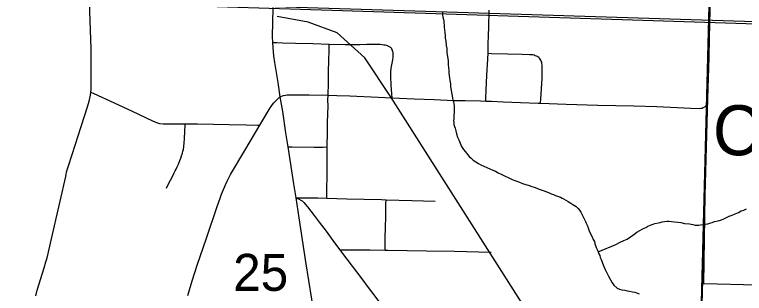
# Model space of a CAD drawing. Extents: x 0 to 34, y 0 to 22.
# Drawn here: x 6.646 to 7.471, y 17.868 to 18.183 of the extents above; entities that cross this region are included whole.
import ezdxf

# ---------------------------------------------------------------- set-up
doc = ezdxf.new("R2010")
doc.units = 0
for name, color, linetype in [('Default', 7, 'Continuous'), ('GM_X_City_Street', 7, 'Continuous'), ('GM_X_County_Road', 7, 'Continuous'), ('GM_X_Minor_River', 7, 'Continuous'), ('GM_X_Rail_Line', 7, 'Continuous'), ('GM_X_Rail_Line_Text', 7, 'Continuous'), ('GM_X_Section', 7, 'Continuous'), ('GM_X_Section_Text', 7, 'Continuous'), ('GM_X_State_Route', 7, 'Continuous'), ('GM_X_Township_Road', 7, 'Continuous')]:
    doc.layers.add(name, color=color, linetype=linetype)

msp = doc.modelspace()

# ---------------------------------------------------------------- linework, layer by layer
at = {"layer": 'Default'}
msp.add_lwpolyline([(7.60459, 17.87419), (7.42494, 17.87863), (7.42778, 18.08122), (7.42892, 18.08581), (7.43183, 18.18894), (7.43397, 18.27475), (7.49781, 18.27299)], dxfattribs=at)
at = {"layer": 'GM_X_City_Street'}
for points in [[(6.66995, 17.86509), (6.6718, 17.87167), (6.67964, 17.89667), (6.68158, 17.90343), (6.68288, 17.90825), (6.68405, 17.91306), (6.68665, 17.92457), (6.69778, 17.9723), (6.70401, 17.9999), (6.70441, 18.00259), (6.70493, 18.00506), (6.70597, 18.00857), (6.70707, 18.01197), (6.71102, 18.02513), (6.72129, 18.05646), (6.72863, 18.07888), (6.73032, 18.08537), (6.73102, 18.08861), (6.73178, 18.09212), (6.73229, 18.09536), (6.73257, 18.09798), (6.73264, 18.10115), (6.73267, 18.11044), (6.73263, 18.14434), (6.73081, 18.19753)], [(7.17857, 18.08537), (7.1787, 18.08827), (7.17915, 18.09805), (7.17991, 18.11436), (7.18078, 18.13301), (7.18105, 18.13942), (7.18133, 18.14872), (7.1817, 18.16082), (7.18191, 18.16789), (7.18212, 18.17483), (7.18234, 18.18201), (7.18252, 18.18822)], [(6.93736, 18.15169), (6.94245, 18.15155), (6.94865, 18.15137), (6.96352, 18.15094), (6.98329, 18.15038), (7.00154, 18.14987), (7.01963, 18.14948), (7.03069, 18.14938), (7.03617, 18.14951), (7.04424, 18.14971), (7.04845, 18.14987), (7.0526, 18.14989), (7.05912, 18.14967), (7.06151, 18.14945), (7.06327, 18.14919), (7.06486, 18.14889), (7.0662, 18.14856), (7.06716, 18.14825), (7.06799, 18.14788), (7.06864, 18.14756), (7.06944, 18.14708), (7.07021, 18.14659), (7.0709, 18.14599), (7.07146, 18.14544), (7.07198, 18.14479), (7.07252, 18.14392)], [(6.99877, 17.97563), (6.99882, 17.97899), (6.99922, 18.00755), (6.9993, 18.02807), (6.99939, 18.03345), (6.9997, 18.05078), (6.99971, 18.06122), (7.00041, 18.07984), (7.00025, 18.08645), (7.00036, 18.09209), (7.00066, 18.10569), (7.00094, 18.11877), (7.00153, 18.143), (7.00154, 18.14485), (7.00154, 18.14987)], [(7.0726, 18.08891), (7.07229, 18.09376), (7.07165, 18.10357), (7.07114, 18.11334), (7.07122, 18.11762), (7.07168, 18.12251), (7.07349, 18.13211), (7.07386, 18.13506), (7.07395, 18.13773), (7.0739, 18.13898), (7.07376, 18.14017), (7.07358, 18.14115), (7.0733, 18.14208), (7.07302, 18.143), (7.07252, 18.14392)], [(7.18105, 18.13942), (7.18497, 18.13932), (7.20314, 18.13885), (7.21981, 18.13834), (7.22813, 18.13825), (7.22997, 18.13814), (7.23167, 18.13794), (7.23304, 18.13756), (7.23443, 18.13711), (7.23647, 18.13618)], [(7.24046, 18.083), (7.24083, 18.08805), (7.24207, 18.11096), (7.24243, 18.12276), (7.24227, 18.1256), (7.24206, 18.12772), (7.24171, 18.12929), (7.24129, 18.13072), (7.24082, 18.13185), (7.24017, 18.13294), (7.23942, 18.13389), (7.23852, 18.13479), (7.23749, 18.13556), (7.23647, 18.13618)], [(6.73229, 18.09536), (6.73547, 18.09392), (6.75877, 18.08341), (6.77911, 18.07405), (6.80179, 18.06289), (6.80461, 18.06175), (6.80635, 18.06105), (6.80994, 18.06019), (6.81408, 18.05982), (6.82519, 18.05966), (6.83246, 18.05972), (6.83863, 18.05978), (6.85275, 18.0595), (6.87091, 18.05912), (6.8885, 18.0588), (6.90795, 18.05843), (6.92065, 18.0582), (6.92337, 18.05815)], [(6.92337, 18.05815), (6.92666, 18.06368), (6.93277, 18.07404), (6.9349, 18.07765), (6.93591, 18.0793), (6.93743, 18.08137), (6.9391, 18.08326), (6.9424, 18.08695), (6.946, 18.09033)], [(6.946, 18.09033), (6.9499, 18.09168), (6.95238, 18.09224), (6.95413, 18.09247), (6.95615, 18.0926), (6.96549, 18.09254), (6.97907, 18.0926), (7.00036, 18.09209)], [(7.00036, 18.09209), (7.01008, 18.09172), (7.02511, 18.09117), (7.05706, 18.08963), (7.0726, 18.08891)], [(7.0726, 18.08891), (7.09754, 18.08806), (7.12026, 18.08714), (7.1422, 18.08623), (7.15525, 18.08595), (7.17256, 18.0856), (7.17857, 18.08537)], [(7.17857, 18.08537), (7.18518, 18.08512), (7.19803, 18.08462), (7.21769, 18.08377), (7.23757, 18.0831), (7.24046, 18.083)], [(7.24046, 18.083), (7.26926, 18.082), (7.30529, 18.08072), (7.34568, 18.07988), (7.3718, 18.07909), (7.41042, 18.07752), (7.41958, 18.07714), (7.42163, 18.07724), (7.42291, 18.07752), (7.42423, 18.07796), (7.4259, 18.07883), (7.42802, 18.08067)], [(6.81786, 17.98696), (6.82057, 17.99242), (6.82406, 17.99943), (6.82657, 18.00424), (6.8277, 18.00664), (6.82868, 18.00849), (6.82982, 18.01094), (6.83125, 18.01398), (6.8329, 18.01807), (6.83389, 18.02079), (6.83481, 18.02346), (6.83578, 18.02654), (6.83629, 18.02869), (6.83679, 18.03074), (6.83733, 18.03391), (6.83781, 18.03797), (6.83825, 18.04264), (6.83863, 18.05143), (6.8387, 18.05832), (6.83863, 18.05978)], [(6.84175, 17.86551), (6.84694, 17.88192), (6.85283, 17.90083), (6.86256, 17.92903), (6.87509, 17.96607), (6.87825, 17.97551), (6.87999, 17.98025), (6.88209, 17.98537), (6.88435, 17.99051), (6.88623, 17.99464), (6.88791, 17.99798), (6.89019, 18.00226), (6.90633, 18.02951), (6.92337, 18.05815)], [(6.95486, 18.03346), (6.95962, 18.03345), (6.98479, 18.03343), (6.99481, 18.03344), (6.99939, 18.03345)], [(6.96381, 17.97584), (6.97508, 17.97588), (6.98879, 17.97592), (6.99877, 17.97563), (7.02165, 17.97496), (7.06071, 17.97387), (7.06586, 17.97374), (7.09481, 17.97303), (7.12151, 17.97221)], [(7.06469, 17.91673), (7.06477, 17.92055), (7.06498, 17.93078), (7.06547, 17.95458), (7.06576, 17.96912), (7.06586, 17.97374)], [(7.01374, 17.917), (7.02071, 17.91698), (7.04763, 17.91694), (7.06469, 17.91673), (7.06803, 17.91669), (7.11156, 17.91616), (7.14332, 17.91562), (7.1703, 17.91502), (7.1845, 17.91465)]]:
    msp.add_lwpolyline(points, dxfattribs=at)
at = {"layer": 'GM_X_County_Road'}
for points in [[(6.96381, 17.97584), (6.96702, 17.97463), (6.96972, 17.97344), (6.97091, 17.97268), (6.97181, 17.97194), (6.97298, 17.97073), (6.97707, 17.96562), (6.98461, 17.95586), (6.99031, 17.94849), (6.99816, 17.93807), (7.00778, 17.92508), (7.01374, 17.917)], [(7.01374, 17.917), (7.01552, 17.91458), (7.0215, 17.90668), (7.03244, 17.8924), (7.03837, 17.88449), (7.04575, 17.87466), (7.04937, 17.86972), (7.06093, 17.85421)]]:
    msp.add_lwpolyline(points, dxfattribs=at)
at = {"layer": 'GM_X_Minor_River'}
for points in [[(7.12949, 18.18644), (7.12977, 18.18301), (7.13007, 18.18034), (7.13075, 18.17766), (7.13108, 18.17575), (7.13103, 18.17385), (7.13133, 18.17118), (7.13164, 18.16889)], [(7.13164, 18.16889), (7.13193, 18.16584), (7.13222, 18.16279), (7.13251, 18.15974), (7.1328, 18.15669), (7.13346, 18.15325), (7.1337, 18.1483), (7.13436, 18.14486), (7.13461, 18.14029), (7.13522, 18.13533), (7.13586, 18.13113), (7.13612, 18.12694), (7.13639, 18.12313), (7.13668, 18.12008), (7.13697, 18.11703), (7.13727, 18.11436), (7.13758, 18.11169), (7.13787, 18.10864), (7.13852, 18.10482), (7.13881, 18.10177), (7.13911, 18.09909), (7.14041, 18.09145), (7.14109, 18.08877), (7.1414, 18.08648), (7.14211, 18.08456), (7.14242, 18.08227), (7.14275, 18.08036), (7.14266, 18.07732), (7.14297, 18.07503), (7.1429, 18.07275), (7.1424, 18.06858), (7.14235, 18.06668), (7.14229, 18.06478), (7.14224, 18.06288), (7.14256, 18.06097), (7.14251, 18.05908), (7.1432, 18.05677), (7.1439, 18.05485), (7.14458, 18.05179), (7.14561, 18.04834), (7.14664, 18.04451), (7.14807, 18.04142), (7.14949, 18.03796), (7.15128, 18.03411), (7.15346, 18.03062), (7.15566, 18.0279), (7.15785, 18.02479), (7.15969, 18.02284), (7.16191, 18.02087), (7.16412, 18.01853), (7.16748, 18.01653), (7.17047, 18.01492), (7.17309, 18.01333), (7.17646, 18.01171), (7.17983, 18.01009), (7.18321, 18.00885), (7.18658, 18.00724), (7.18959, 18.00601), (7.19258, 18.0044), (7.19595, 18.00278), (7.19969, 18.00077), (7.20457, 17.99873), (7.20831, 17.99672), (7.21244, 17.99508), (7.21658, 17.99382), (7.21995, 17.9922), (7.22371, 17.99096), (7.22748, 17.98971), (7.23049, 17.98886), (7.23313, 17.98802), (7.23989, 17.98555), (7.24327, 17.98431), (7.24628, 17.98308), (7.24928, 17.98186), (7.25228, 17.98063), (7.25492, 17.97979), (7.25716, 17.97859), (7.26054, 17.97735), (7.2628, 17.97652), (7.26468, 17.97571), (7.26655, 17.97489), (7.26916, 17.9733), (7.27178, 17.9717), (7.27477, 17.97009), (7.277, 17.96851), (7.27887, 17.96731), (7.28073, 17.96612), (7.28294, 17.96377), (7.2844, 17.96183), (7.28587, 17.95989), (7.28694, 17.95758), (7.28839, 17.95525), (7.29018, 17.9514), (7.29125, 17.94909), (7.29196, 17.94717), (7.29303, 17.94485), (7.29409, 17.94216), (7.29551, 17.9387), (7.29693, 17.93524), (7.29872, 17.93176), (7.29978, 17.92869)], [(7.30545, 17.91484), (7.32544, 17.92301), (7.33046, 17.92591), (7.33469, 17.92768), (7.33815, 17.9291), (7.34591, 17.93459), (7.3494, 17.93715), (7.35249, 17.93896), (7.35519, 17.9404), (7.3575, 17.94148), (7.35943, 17.94256), (7.36175, 17.94402), (7.36367, 17.94472), (7.36559, 17.94543), (7.36751, 17.94613), (7.36943, 17.94684), (7.37364, 17.94785), (7.37555, 17.94818), (7.37785, 17.94888), (7.38052, 17.94918), (7.38318, 17.94948), (7.38584, 17.9494), (7.3885, 17.94933), (7.3919, 17.94885), (7.39568, 17.94836), (7.39909, 17.94788), (7.40324, 17.947), (7.40892, 17.94646), (7.41232, 17.9456), (7.41496, 17.94514), (7.41724, 17.94508), (7.41914, 17.94502), (7.42105, 17.94535), (7.42371, 17.94565), (7.42677, 17.94632), (7.42944, 17.94663), (7.43174, 17.94732), (7.43442, 17.948), (7.43711, 17.94907), (7.44132, 17.95009), (7.44476, 17.95113), (7.44746, 17.95219), (7.45053, 17.95362), (7.45361, 17.95506), (7.45707, 17.95648), (7.46053, 17.9579), (7.46399, 17.95932), (7.46708, 17.96113), (7.47015, 17.96218), (7.47323, 17.96362)], [(7.29978, 17.92869), (7.30123, 17.92637), (7.30192, 17.92407), (7.30263, 17.92215), (7.30332, 17.91984), (7.30439, 17.91753), (7.30545, 17.91484), (7.30614, 17.91254), (7.30723, 17.91061), (7.30792, 17.9083), (7.309, 17.90637), (7.30971, 17.90445), (7.3104, 17.90215), (7.31181, 17.89831), (7.31361, 17.89483), (7.31539, 17.89098), (7.31719, 17.8875), (7.32153, 17.87977), (7.32335, 17.87706), (7.32706, 17.87391), (7.32968, 17.8727), (7.33231, 17.87186), (7.33572, 17.87138), (7.33836, 17.87092), (7.34101, 17.87047), (7.3444, 17.86961), (7.34705, 17.86915), (7.34892, 17.86834), (7.35194, 17.86749)]]:
    msp.add_lwpolyline(points, dxfattribs=at)
at = {"layer": 'GM_X_Rail_Line'}
for points in [[(5.35106, 18.04678), (5.42697, 18.05726), (5.49719, 18.07056), (5.53225, 18.08015), (5.65152, 18.10637), (5.73788, 18.12707), (5.81793, 18.14439), (5.93217, 18.17031), (5.99402, 18.1844), (6.05215, 18.19648), (6.1174, 18.20707), (6.18087, 18.21236), (6.22876, 18.21488), (6.43848, 18.20909), (6.70994, 18.20004), (7.11057, 18.18722), (7.54287, 18.1734)], [(5.35138, 18.04432), (5.42737, 18.05481), (5.49775, 18.06813), (5.53284, 18.07774), (5.65207, 18.10395), (5.73843, 18.12465), (5.81847, 18.14196), (5.93272, 18.16789), (5.99455, 18.18197), (6.05261, 18.19404), (6.1177, 18.2046), (6.18104, 18.20988), (6.22879, 18.21239), (6.43841, 18.20661), (6.70986, 18.19756), (7.11049, 18.18474), (7.54279, 18.17091)], [(8.31912, 14.1), (8.26519, 14.29151), (7.99841, 15.30059), (7.77868, 16.11858), (7.54638, 16.95196), (7.4475, 17.3725), (7.39862, 17.49992), (7.33889, 17.63816), (7.26967, 17.77776), (7.07158, 18.08945), (7.04174, 18.13417), (7.01055, 18.16261), (6.97802, 18.17479), (6.94272, 18.181)]]:
    msp.add_lwpolyline(points, dxfattribs=at)
at = {"layer": 'GM_X_Section'}
for points in [[(6.44087, 18.40636), (7.43595, 18.38371), (7.41005, 17.37616), (6.41184, 17.39355)], [(7.43595, 18.38371), (8.36925, 18.36041), (8.34451, 17.35473), (7.41005, 17.37616)]]:
    msp.add_lwpolyline(points, close=True, dxfattribs=at)
at = {"layer": 'GM_X_State_Route'}
for points in [[(6.93797, 18.19128), (6.93798, 18.19024), (6.93765, 18.17466), (6.9372, 18.15856), (6.93736, 18.15169), (6.93777, 18.14592), (6.93878, 18.13651), (6.93988, 18.12918), (6.94349, 18.10625), (6.946, 18.09033), (6.94866, 18.07342), (6.95236, 18.04948), (6.95486, 18.03346), (6.96137, 17.99178), (6.96381, 17.97584)], [(6.96381, 17.97584), (6.96725, 17.95348), (6.97489, 17.90348), (6.98158, 17.86129), (6.98306, 17.85193), (6.98614, 17.83232), (6.98941, 17.81223), (6.99091, 17.80304), (6.99351, 17.78492), (6.99409, 17.7809), (7.00317, 17.72382), (7.01517, 17.64863), (7.0164, 17.64095), (7.02908, 17.55926), (7.0376, 17.50526), (7.04155, 17.48131), (7.04755, 17.44136), (7.05723, 17.38071)]]:
    msp.add_lwpolyline(points, dxfattribs=at)
at = {"layer": 'GM_X_Township_Road'}
for points in [[(7.40018, 16.98823), (7.40941, 17.37521), (7.40938, 17.39008), (7.4094, 17.39112), (7.42325, 17.8824), (7.42904, 18.08817), (7.43041, 18.13465), (7.43105, 18.15765), (7.43183, 18.18894), (7.43413, 18.28112), (7.43431, 18.28821), (7.43473, 18.31426), (7.43522, 18.3416), (7.43554, 18.35764), (7.43626, 18.3862), (7.44548, 18.73809), (7.19617, 18.79556), (7.02485, 18.79774), (6.80642, 18.77572), (6.4444, 18.86381)], [(7.44741, 18.8622), (7.44548, 18.73809), (7.43626, 18.3862), (7.43554, 18.35764), (7.43522, 18.3416), (7.43473, 18.31426), (7.43431, 18.28821), (7.43413, 18.28112), (7.43183, 18.18894), (7.43105, 18.15765), (7.43041, 18.13465), (7.42904, 18.08817), (7.42325, 17.8824), (7.4094, 17.39112), (7.40938, 17.39008), (7.40941, 17.37521), (7.40018, 16.98823)], [(7.42802, 18.08067), (7.42871, 18.08307), (7.42898, 18.08508), (7.42928, 18.08762), (7.43064, 18.1341), (7.43128, 18.15709), (7.43207, 18.18839)]]:
    msp.add_lwpolyline(points, dxfattribs=at)

# ---------------------------------------------------------------- texts
at = {"layer": 'GM_X_Rail_Line_Text'}
msp.add_text('CSX', height=0.056629, rotation=357.88901, dxfattribs=at).set_placement((7.43411, 18.02514))
at = {"layer": 'GM_X_Section_Text'}
msp.add_text('25', height=0.041856, rotation=0.00001, dxfattribs=at).set_placement((6.89305, 17.87073))

doc.saveas('drawing.dxf')
